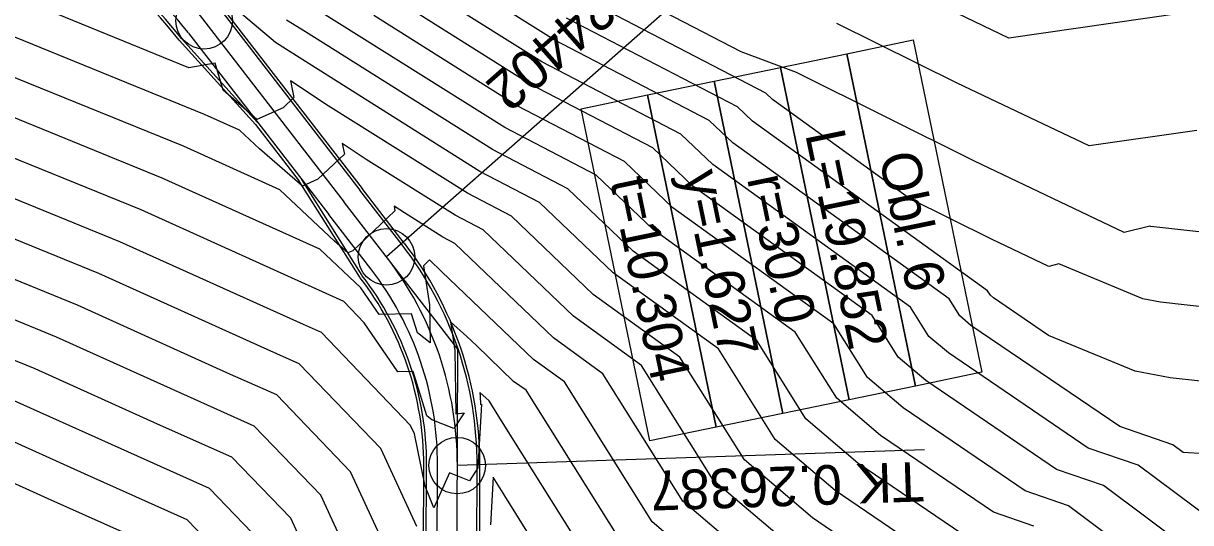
# Model space of a CAD drawing. Extents: x -549394 to -546608, y -1037055 to -1033629.
# Drawn here: x -546964.3 to -546861.1, y -1035948.7 to -1035904.5 of the extents above; entities that cross this region are included whole.
import ezdxf

# ---------------------------------------------------------------- set-up
doc = ezdxf.new("R2010")
doc.units = 0
for name, color, linetype in [('hlavni_vrst', 7, 'Continuous'), ('norm_vrst', 7, 'Continuous'), ('POLYGONY_SITUACE_PO', 7, 'Continuous'), ('x_navrh_C31', 7, 'Continuous'), ('x_osa_C31', 7, 'Continuous'), ('x_popis_oblouky_C31', 7, 'Continuous')]:
    doc.layers.add(name, color=color, linetype=linetype)

msp = doc.modelspace()

# ---------------------------------------------------------------- linework, layer by layer
at = {"layer": 'hlavni_vrst'}
for p, q in [((-546898.67, -1035910.66), (-546915.18, -1035902.09)), ((-546920.66, -1035911.78), (-546933.34, -1035903.81)), ((-546948.31, -1035912.56), (-546965.11, -1035905.72)), ((-546898.07, -1035911.23), (-546898.67, -1035910.66)), ((-546911.17, -1035916.71), (-546920.66, -1035911.78)), ((-546885.94, -1035919.98), (-546898.07, -1035911.23)), ((-546945.21, -1035913.96), (-546948.31, -1035912.56)), ((-546943.46, -1035915.61), (-546945.21, -1035913.96)), ((-546939.66, -1035918.9), (-546943.46, -1035915.61)), ((-546935.94, -1035916.07), (-546938.28, -1035918.29)), ((-546936.13, -1035915.13), (-546935.94, -1035916.07)), ((-546934.01, -1035916.53), (-546936.13, -1035915.13)), ((-546926.14, -1035921.47), (-546934.01, -1035916.53)), ((-546906.88, -1035920.82), (-546911.17, -1035916.71)), ((-546938.28, -1035918.29), (-546939.66, -1035918.9)), ((-546878.69, -1035923.59), (-546885.94, -1035919.98)), ((-546892.65, -1035931.08), (-546906.88, -1035920.82)), ((-546957.68, -1035926.62), (-546969.22, -1035921.92)), ((-546923.67, -1035922.75), (-546926.14, -1035921.47)), ((-546915.68, -1035930.4), (-546923.67, -1035922.75)), ((-546873.62, -1035926), (-546878.69, -1035923.59)), ((-546872.75, -1035925.78), (-546873.62, -1035926)), ((-546865.3, -1035928.86), (-546872.75, -1035925.78)), ((-546942.78, -1035933.34), (-546957.68, -1035926.62)), ((-546863.74, -1035929.16), (-546865.3, -1035928.86)), ((-546857.86, -1035929.81), (-546863.74, -1035929.16)), ((-546909.66, -1035934.75), (-546915.68, -1035930.4)), ((-546889.67, -1035935.83), (-546892.65, -1035931.08)), ((-546939.95, -1035934.6), (-546942.78, -1035933.34)), ((-546932.73, -1035942.1), (-546939.95, -1035934.6)), ((-546903.28, -1035944.93), (-546909.66, -1035934.75)), ((-546886.51, -1035938.51), (-546889.67, -1035935.83)), ((-546875.73, -1035945.85), (-546886.51, -1035938.51)), ((-546958.93, -1035944.34), (-546967.05, -1035940.68)), ((-546929.53, -1035949), (-546932.73, -1035942.1)), ((-546949.85, -1035948.39), (-546958.93, -1035944.34)), ((-546922.77, -1035944.62), (-546923.02, -1035948.86)), ((-546921.74, -1035946.29), (-546922.77, -1035944.62)), ((-546896.52, -1035950.68), (-546903.28, -1035944.93)), ((-546871.88, -1035947.16), (-546875.73, -1035945.85)), ((-546916.89, -1035954.03), (-546921.74, -1035946.29)), ((-546853.89, -1035960.59), (-546871.88, -1035947.16)), ((-546946, -1035952.39), (-546949.85, -1035948.39))]:
    msp.add_line(p, q, dxfattribs=at)
at = {"layer": 'norm_vrst'}
for p, q in [((-546900.84, -1035907.02), (-546914.08, -1035900.15)), ((-546917.37, -1035905.97), (-546924.26, -1035901.64)), ((-546949.7, -1035908.42), (-546964.29, -1035902.48)), ((-546942.04, -1035906.19), (-546946.54, -1035902.35)), ((-546936.37, -1035904.54), (-546940.3, -1035902.06)), ((-546918.47, -1035907.91), (-546927.29, -1035902.36)), ((-546855.2, -1035902.63), (-546877.17, -1035905.8)), ((-546919.56, -1035909.84), (-546930.31, -1035903.09)), ((-546877.17, -1035905.8), (-546883.25, -1035902.9)), ((-546939.39, -1035905.26), (-546941.06, -1035904.21)), ((-546921.76, -1035913.72), (-546936.37, -1035904.54)), ((-546901.17, -1035911.87), (-546916.28, -1035904.03)), ((-546881.73, -1035909.8), (-546892.38, -1035904.5)), ((-546922.85, -1035915.66), (-546939.39, -1035905.26)), ((-546940.75, -1035907.03), (-546942.04, -1035906.19)), ((-546903.67, -1035913.08), (-546917.37, -1035905.97)), ((-546923.95, -1035917.59), (-546940.75, -1035907.03)), ((-546895.96, -1035908.85), (-546900.84, -1035907.02)), ((-546947.37, -1035908.01), (-546949.7, -1035908.42)), ((-546946.68, -1035910.4), (-546947.37, -1035908.01)), ((-546906.17, -1035914.29), (-546918.47, -1035907.91)), ((-546880.21, -1035916.69), (-546895.96, -1035908.85)), ((-546950.18, -1035915.37), (-546965.94, -1035908.96)), ((-546940.72, -1035909.58), (-546940.41, -1035911.06)), ((-546937.38, -1035911.78), (-546940.72, -1035909.58)), ((-546908.67, -1035915.5), (-546919.56, -1035909.84)), ((-546870.07, -1035915.34), (-546881.73, -1035909.8)), ((-546943.69, -1035912.99), (-546946.68, -1035910.4)), ((-546941.36, -1035911.97), (-546943.69, -1035912.99)), ((-546940.41, -1035911.06), (-546941.36, -1035911.97)), ((-546925.04, -1035919.53), (-546937.38, -1035911.78)), ((-546899.83, -1035913.15), (-546901.17, -1035911.87)), ((-546952.06, -1035918.19), (-546966.76, -1035912.2)), ((-546913.67, -1035917.91), (-546921.76, -1035913.72)), ((-546901.59, -1035915.07), (-546903.67, -1035913.08)), ((-546879.04, -1035928.14), (-546899.83, -1035913.15)), ((-546860.53, -1035913.97), (-546870.07, -1035915.34)), ((-546903.35, -1035916.98), (-546906.17, -1035914.29)), ((-546882.45, -1035928.87), (-546901.59, -1035915.07)), ((-546953.93, -1035921), (-546967.58, -1035915.44)), ((-546941.66, -1035919.22), (-546950.18, -1035915.37)), ((-546916.17, -1035919.12), (-546922.85, -1035915.66)), ((-546905.11, -1035918.9), (-546908.67, -1035915.5)), ((-546885.85, -1035929.61), (-546903.35, -1035916.98)), ((-546866.96, -1035922.99), (-546880.21, -1035916.69)), ((-546938.11, -1035924.48), (-546952.06, -1035918.19)), ((-546918.67, -1035920.33), (-546923.95, -1035917.59)), ((-546908.64, -1035922.74), (-546913.67, -1035917.91)), ((-546955.8, -1035923.81), (-546968.4, -1035918.68)), ((-546936.83, -1035923.77), (-546941.66, -1035919.22)), ((-546910.4, -1035924.65), (-546916.17, -1035919.12)), ((-546889.25, -1035930.34), (-546905.11, -1035918.9)), ((-546921.17, -1035921.54), (-546925.04, -1035919.53)), ((-546936.32, -1035928.94), (-546953.93, -1035921)), ((-546931.47, -1035921.08), (-546935.2, -1035924.61)), ((-546931.55, -1035920.67), (-546931.47, -1035921.08)), ((-546930.63, -1035921.27), (-546931.55, -1035920.67)), ((-546927.24, -1035923.41), (-546930.63, -1035921.27)), ((-546912.16, -1035926.57), (-546918.67, -1035920.33)), ((-546913.92, -1035928.49), (-546921.17, -1035921.54)), ((-546896.05, -1035931.81), (-546908.64, -1035922.74)), ((-546864.69, -1035922.43), (-546866.96, -1035922.99)), ((-546864.62, -1035922.46), (-546864.69, -1035922.43)), ((-546864.6, -1035922.47), (-546864.62, -1035922.46)), ((-546855.53, -1035923.47), (-546864.6, -1035922.47)), ((-546939.55, -1035931.14), (-546955.8, -1035923.81)), ((-546935.63, -1035924.8), (-546936.83, -1035923.77)), ((-546926.17, -1035923.96), (-546927.24, -1035923.41)), ((-546917.45, -1035932.32), (-546926.17, -1035923.96)), ((-546959.55, -1035929.43), (-546970.05, -1035925.16)), ((-546934.5, -1035927.88), (-546938.11, -1035924.48)), ((-546935.2, -1035924.61), (-546935.63, -1035924.8)), ((-546928.4, -1035925.42), (-546928.95, -1035925.94)), ((-546927.33, -1035926.46), (-546928.4, -1035925.42)), ((-546899.46, -1035932.54), (-546910.4, -1035924.65)), ((-546928.95, -1035925.94), (-546928.41, -1035929.38)), ((-546919.21, -1035934.24), (-546927.33, -1035926.46)), ((-546902.86, -1035933.28), (-546912.16, -1035926.57)), ((-546961.42, -1035932.24), (-546970.87, -1035928.39)), ((-546932.88, -1035930.26), (-546934.5, -1035927.88)), ((-546906.26, -1035934.01), (-546913.92, -1035928.49)), ((-546878.78, -1035928.55), (-546879.04, -1035928.14)), ((-546946.01, -1035935.54), (-546959.55, -1035929.43)), ((-546935.99, -1035929.09), (-546936.32, -1035928.94)), ((-546934.18, -1035930.98), (-546935.99, -1035929.09)), ((-546928.41, -1035929.38), (-546928.35, -1035932.75)), ((-546881.51, -1035930.37), (-546882.45, -1035928.87)), ((-546878.51, -1035928.78), (-546878.78, -1035928.55)), ((-546873.65, -1035932.09), (-546878.51, -1035928.78)), ((-546930, -1035930.19), (-546932.88, -1035930.26)), ((-546929.47, -1035931.87), (-546930, -1035930.19)), ((-546886.95, -1035934.01), (-546889.25, -1035930.34)), ((-546884.23, -1035932.19), (-546885.85, -1035929.61)), ((-546880.51, -1035931.22), (-546881.51, -1035930.37)), ((-546937.97, -1035931.84), (-546939.55, -1035931.14)), ((-546931.22, -1035935.33), (-546934.18, -1035930.98)), ((-546926.56, -1035930.9), (-546926.16, -1035933.43)), ((-546925.1, -1035932.19), (-546926.56, -1035930.9)), ((-546867.35, -1035940.16), (-546880.51, -1035931.22)), ((-546963.3, -1035935.05), (-546971.69, -1035931.63)), ((-546949.24, -1035937.74), (-546961.42, -1035932.24)), ((-546930.08, -1035940.05), (-546937.97, -1035931.84)), ((-546928.35, -1035932.75), (-546929.47, -1035931.87)), ((-546924.23, -1035933.03), (-546925.1, -1035932.19)), ((-546913.07, -1035935.48), (-546917.45, -1035932.32)), ((-546895.11, -1035939.47), (-546899.46, -1035932.54)), ((-546892.39, -1035937.65), (-546896.05, -1035931.81)), ((-546882.51, -1035933.65), (-546884.23, -1035932.19)), ((-546865.98, -1035935.26), (-546873.65, -1035932.09)), ((-546926.16, -1035933.43), (-546926.07, -1035939.03)), ((-546920.97, -1035936.16), (-546924.23, -1035933.03)), ((-546897.83, -1035941.29), (-546902.86, -1035933.28)), ((-546870.15, -1035942.06), (-546882.51, -1035933.65)), ((-546916.47, -1035936.21), (-546919.21, -1035934.24)), ((-546900.56, -1035943.11), (-546906.26, -1035934.01)), ((-546884.51, -1035936.08), (-546886.95, -1035934.01)), ((-546952.47, -1035939.94), (-546963.3, -1035935.05)), ((-546941.93, -1035937.36), (-546946.01, -1035935.54)), ((-546929.87, -1035935.3), (-546931.22, -1035935.33)), ((-546928.65, -1035939.22), (-546929.87, -1035935.3)), ((-546906, -1035946.75), (-546913.07, -1035935.48)), ((-546862.88, -1035935.86), (-546865.98, -1035935.26)), ((-546919.87, -1035936.95), (-546920.97, -1035936.16)), ((-546908.72, -1035948.57), (-546916.47, -1035936.21)), ((-546872.94, -1035943.95), (-546884.51, -1035936.08)), ((-546860.2, -1035936.15), (-546862.88, -1035935.86)), ((-546943.91, -1035940.12), (-546949.24, -1035937.74)), ((-546935.39, -1035944.16), (-546941.93, -1035937.36)), ((-546923.97, -1035937.14), (-546923.92, -1035937.47)), ((-546923.13, -1035937.88), (-546923.97, -1035937.14)), ((-546923.92, -1035937.47), (-546923.9, -1035938.2)), ((-546911.44, -1035950.39), (-546919.87, -1035936.95)), ((-546888.52, -1035940.95), (-546892.39, -1035937.65)), ((-546955.7, -1035942.14), (-546965.17, -1035937.87)), ((-546923.8, -1035938.19), (-546924.13, -1035943.82)), ((-546923.9, -1035938.2), (-546923.8, -1035938.19)), ((-546922.05, -1035939.64), (-546923.13, -1035937.88)), ((-546928.2, -1035939.57), (-546928.65, -1035939.22)), ((-546926.26, -1035940.34), (-546928.2, -1035939.57)), ((-546925.36, -1035938.95), (-546926.26, -1035940.34)), ((-546926.07, -1035939.03), (-546925.36, -1035938.95)), ((-546914.16, -1035952.21), (-546922.05, -1035939.64)), ((-546890.52, -1035943.38), (-546895.11, -1035939.47)), ((-546945.89, -1035942.87), (-546952.47, -1035939.94)), ((-546938.04, -1035946.22), (-546943.91, -1035940.12)), ((-546929.74, -1035940.79), (-546930.08, -1035940.05)), ((-546928.8, -1035945.43), (-546929.74, -1035940.79)), ((-546862.65, -1035941.77), (-546867.35, -1035940.16)), ((-546892.52, -1035945.81), (-546897.83, -1035941.29)), ((-546878.53, -1035947.74), (-546888.52, -1035940.95)), ((-546861.74, -1035942.45), (-546862.65, -1035941.77)), ((-546947.87, -1035945.63), (-546955.7, -1035942.14)), ((-546940.69, -1035948.27), (-546945.89, -1035942.87)), ((-546865.73, -1035943.56), (-546870.15, -1035942.06)), ((-546859.82, -1035942.58), (-546861.74, -1035942.45)), ((-546962.16, -1035946.54), (-546968.92, -1035943.49)), ((-546924.13, -1035943.82), (-546924.86, -1035944.95)), ((-546894.52, -1035948.24), (-546900.56, -1035943.11)), ((-546881.32, -1035949.63), (-546890.52, -1035943.38)), ((-546868.8, -1035945.36), (-546872.94, -1035943.95)), ((-546859.12, -1035948.5), (-546865.73, -1035943.56)), ((-546929.33, -1035957.21), (-546935.39, -1035944.16)), ((-546926.65, -1035944.25), (-546928.04, -1035947.34)), ((-546924.86, -1035944.95), (-546926.65, -1035944.25)), ((-546943.35, -1035950.33), (-546947.87, -1035945.63)), ((-546928.04, -1035947.34), (-546928.8, -1035945.43)), ((-546884.11, -1035951.53), (-546892.52, -1035945.81)), ((-546856.51, -1035954.54), (-546868.8, -1035945.36)), ((-546951.83, -1035951.14), (-546962.16, -1035946.54)), ((-546931.84, -1035959.58), (-546938.04, -1035946.22)), ((-546898.52, -1035953.11), (-546906, -1035946.75)), ((-546874.96, -1035948.96), (-546878.53, -1035947.74)), ((-546935.2, -1035960.1), (-546940.69, -1035948.27)), ((-546900.52, -1035955.54), (-546908.72, -1035948.57)), ((-546886.91, -1035953.42), (-546894.52, -1035948.24))]:
    msp.add_line(p, q, dxfattribs=at)
at = {"layer": 'POLYGONY_SITUACE_PO'}
for centre in [(-546948.35, -1035904.28), (-546932.22, -1035925.15), (-546925.96, -1035943.61)]:
    msp.add_circle(centre, 2.5, dxfattribs=at)
at = {"layer": 'x_navrh_C31'}
for p, q in [((-546946.97, -1035903.21), (-546934.57, -1035919.25)), ((-546946.77, -1035903.06), (-546934.37, -1035919.1)), ((-546949.74, -1035905.36), (-546943.61, -1035913.27)), ((-546950.55, -1035906), (-546943.81, -1035913.43)), ((-546950.36, -1035905.84), (-546943.62, -1035913.27)), ((-546943.81, -1035913.43), (-546939.93, -1035918.45)), ((-546943.61, -1035913.27), (-546937.33, -1035921.4)), ((-546934.58, -1035926.95), (-546939.93, -1035918.45)), ((-546934.37, -1035926.81), (-546939.72, -1035918.31)), ((-546930.83, -1035924.08), (-546934.57, -1035919.25)), ((-546933.6, -1035926.22), (-546937.33, -1035921.4)), ((-546928.97, -1035958.63), (-546928.92, -1035943.59)), ((-546928.72, -1035958.63), (-546928.67, -1035943.6)), ((-546927.75, -1035958.63), (-546927.7, -1035943.6)), ((-546924.25, -1035958.64), (-546924.2, -1035943.61))]:
    msp.add_line(p, q, dxfattribs=at)
for points in [[(-546930.64, -1035923.93), (-546934.37, -1035919.1)], [(-546924, -1035958.64), (-546923.95, -1035943.61)]]:
    msp.add_lwpolyline(points, dxfattribs=at)
for centre, radius, start, end in [((-546980, -1035928.75), 38.25, 37.7126, 73.4173), ((-546980, -1035928.75), 37.46, 37.7126, 73.4173), ((-546980, -1035928.75), 37.21, 37.6975, 58.7657), ((-546955.95, -1035943.5), 31.75, 359.7992, 37.7126), ((-546955.95, -1035943.5), 32, 359.7992, 37.7126), ((-546955.95, -1035943.5), 28.25, 359.7992, 37.7126), ((-546955.95, -1035943.5), 27.03, 359.7992, 37.7126), ((-546955.95, -1035943.5), 27.28, 359.7992, 37.7126)]:
    msp.add_arc(centre, radius, start, end, dxfattribs=at)
at = {"layer": 'x_osa_C31'}
for points in [[(-546956.23, -1035894.09), (-546935.95, -1035920.32)], [(-547007, -1036074.62), (-546946.36, -1035990.32), (-546926.05, -1035971.84), (-546925.92, -1035933.3), (-546935.95, -1035920.32)]]:
    msp.add_lwpolyline(points, dxfattribs=at)
msp.add_arc((-546955.95, -1035943.5), 30, 359.7992, 37.7126, dxfattribs=at)
at = {"layer": 'x_popis_oblouky_C31'}
for points in [[(-546901.18, -1035897.79), (-546932.22, -1035925.15)], [(-546884.61, -1035942.2), (-546925.96, -1035943.61)]]:
    msp.add_lwpolyline(points, dxfattribs=at)
for points in [[(-546885.62, -1035905.97), (-546879.54, -1035935.35), (-546885.42, -1035936.57), (-546891.49, -1035907.19)], [(-546891.49, -1035907.19), (-546885.42, -1035936.57), (-546891.3, -1035937.78), (-546897.37, -1035908.4)], [(-546897.37, -1035908.4), (-546891.3, -1035937.78), (-546897.17, -1035939), (-546903.24, -1035909.62)], [(-546903.24, -1035909.62), (-546897.17, -1035939), (-546903.05, -1035940.21), (-546909.12, -1035910.83)], [(-546909.12, -1035910.83), (-546903.05, -1035940.21), (-546908.92, -1035941.43), (-546915, -1035912.05)]]:
    msp.add_lwpolyline(points, close=True, dxfattribs=at)

# ---------------------------------------------------------------- texts
for s, rotation, p in [('TK 0.24402', 221.3899, (-546905.49, -1035893.86)), ('L=19.852', 281.7004, (-546895.19, -1035914.29)), ('Obl. 6', 281.7004, (-546888.66, -1035916.21)), ('t=10.304', 281.7004, (-546912.44, -1035918.45)), ('y=1.627', 281.7004, (-546906.08, -1035917.85)), ('r=30.0', 281.7004, (-546900.33, -1035918.21)), ('TK 0.26387', 181.9469, (-546884.72, -1035943.27))]:
    msp.add_text(s, height=3.5, rotation=rotation, dxfattribs=at).set_placement(p)

doc.saveas('drawing.dxf')
